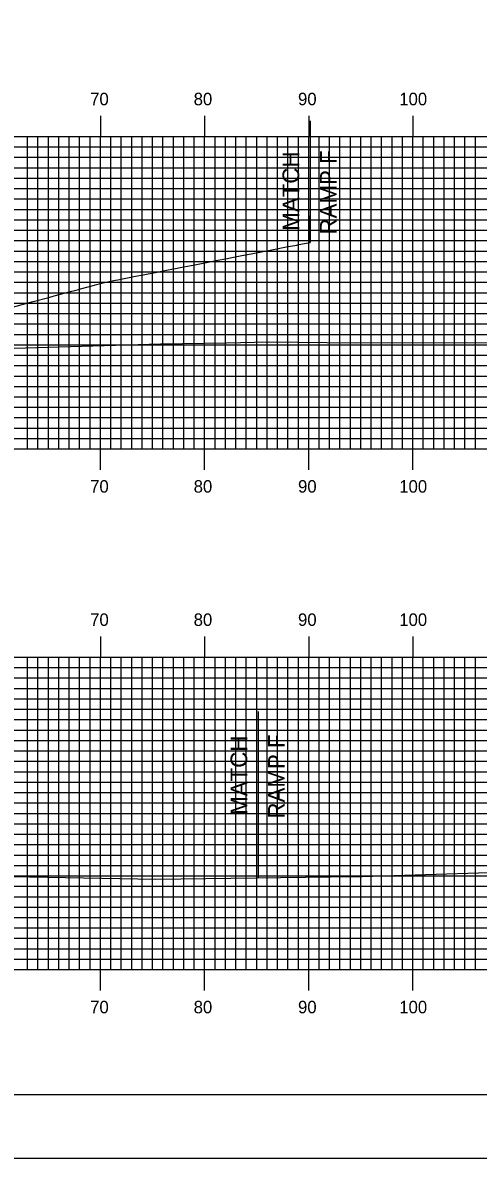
# Model space of a CAD drawing. Extents: x 1757856 to 1758199, y 442591 to 442811.
# Drawn here: x 1758084.2 to 1758127.9, y 442590.5 to 442699.6 of the extents above; entities that cross this region are included whole.
import ezdxf

# ---------------------------------------------------------------- set-up
doc = ezdxf.new("R2010")
doc.units = 0
for name, color, linetype in [('ANNOTATION', 7, 'Continuous'), ('BORDER', 7, 'Continuous'), ('D_Roadway_Centerline', 7, 'Continuous'), ('D_Roadway_FinishedGrade', 7, 'Continuous'), ('D_Roadway_SubGrade', 7, 'Continuous'), ('H_V ANNOTATION', 7, 'Continuous'), ('MAJOR', 7, 'Continuous'), ('MINOR', 7, 'Continuous'), ('PLOT BOUNDARY', 7, 'Continuous'), ('S_Roadway_Centerline', 7, 'Continuous')]:
    doc.layers.add(name, color=color, linetype=linetype)

msp = doc.modelspace()

# ---------------------------------------------------------------- linework, layer by layer
at = {"layer": 'BORDER'}
msp.add_lwpolyline([(1757872.02, 442596.67), (1758192.02, 442596.67), (1758192.02, 442806.67), (1757872.02, 442806.67)], close=True, dxfattribs=at)
at = {"layer": 'D_Roadway_Centerline'}
msp.add_lwpolyline([(1758083.16, 442672.28), (1758084.46, 442672.63), (1758085.17, 442672.82), (1758086.67, 442673.22), (1758087.17, 442673.36), (1758088.86, 442673.81), (1758089.15, 442673.89), (1758089.64, 442674.02), (1758089.7, 442674.03), (1758091.05, 442674.39), (1758091.12, 442674.41), (1758092.15, 442674.68), (1758093.07, 442674.87), (1758093.3, 442674.91), (1758095, 442675.25), (1758095.71, 442675.38), (1758096.87, 442675.61), (1758096.89, 442675.62), (1758096.91, 442675.62), (1758098.12, 442675.86), (1758098.81, 442675.99), (1758099.26, 442676.08), (1758100.69, 442676.36), (1758101.47, 442676.51), (1758102.56, 442676.72), (1758102.71, 442676.75), (1758103.81, 442676.97), (1758104.25, 442677.05), (1758104.41, 442677.08), (1758105.04, 442677.21), (1758106.25, 442677.44), (1758107.08, 442677.6), (1758108.07, 442677.79), (1758109.47, 442678.06), (1758109.87, 442678.14), (1758110.46, 442678.25), (1758110.55, 442678.27), (1758110.67, 442678.29), (1758111.75, 442678.5)], dxfattribs=at)
at = {"layer": 'D_Roadway_FinishedGrade'}
msp.add_line((1758111.75, 442678.5), (1758111.75, 442681.05), dxfattribs=at)
at = {"layer": 'D_Roadway_SubGrade'}
for p, q in [((1758111.75, 442690.19), (1758111.75, 442678.5)), ((1758106.76, 442633.44), (1758106.76, 442617.49))]:
    msp.add_line(p, q, dxfattribs=at)
at = {"layer": 'MAJOR'}
for p, q in [((1758091.62, 442690.67), (1758091.62, 442688.67)), ((1758101.62, 442690.67), (1758101.62, 442688.67)), ((1758111.62, 442690.67), (1758111.62, 442688.67)), ((1758121.62, 442690.67), (1758121.62, 442688.67)), ((1757881.62, 442688.67), (1758161.62, 442688.67)), ((1757881.62, 442688.67), (1758161.62, 442688.67)), ((1758091.62, 442658.67), (1758091.62, 442688.67)), ((1758101.62, 442658.67), (1758101.62, 442688.67)), ((1758111.62, 442658.67), (1758111.62, 442688.67)), ((1758121.62, 442658.67), (1758121.62, 442688.67)), ((1757881.62, 442683.67), (1758161.62, 442683.67)), ((1757881.62, 442678.67), (1758161.62, 442678.67)), ((1757881.62, 442673.67), (1758161.62, 442673.67)), ((1757881.62, 442668.67), (1758161.62, 442668.67)), ((1757881.62, 442663.67), (1758161.62, 442663.67)), ((1757881.62, 442658.67), (1758161.62, 442658.67)), ((1757881.62, 442658.67), (1758161.62, 442658.67)), ((1758091.62, 442656.66), (1758091.62, 442658.67)), ((1758101.62, 442656.66), (1758101.62, 442658.67)), ((1758111.62, 442656.66), (1758111.62, 442658.67)), ((1758121.62, 442656.66), (1758121.62, 442658.67)), ((1758091.62, 442640.67), (1758091.62, 442638.67)), ((1758101.62, 442640.67), (1758101.62, 442638.67)), ((1758111.62, 442640.67), (1758111.62, 442638.67)), ((1758121.62, 442640.67), (1758121.62, 442638.67)), ((1757881.62, 442638.67), (1758161.62, 442638.67)), ((1757881.62, 442638.67), (1758161.62, 442638.67)), ((1758091.62, 442608.67), (1758091.62, 442638.67)), ((1758101.62, 442608.67), (1758101.62, 442638.67)), ((1758111.62, 442608.67), (1758111.62, 442638.67)), ((1758121.62, 442608.67), (1758121.62, 442638.67)), ((1757881.62, 442633.67), (1758161.62, 442633.67)), ((1757881.62, 442628.67), (1758161.62, 442628.67)), ((1757881.62, 442623.67), (1758161.62, 442623.67)), ((1757881.62, 442618.67), (1758161.62, 442618.67)), ((1757881.62, 442613.67), (1758161.62, 442613.67)), ((1757881.62, 442608.67), (1758161.62, 442608.67)), ((1757881.62, 442608.67), (1758161.62, 442608.67)), ((1758091.62, 442606.66), (1758091.62, 442608.67)), ((1758101.62, 442606.66), (1758101.62, 442608.67)), ((1758111.62, 442606.66), (1758111.62, 442608.67)), ((1758121.62, 442606.66), (1758121.62, 442608.67))]:
    msp.add_line(p, q, dxfattribs=at)
at = {"layer": 'MINOR'}
for p, q in [((1758084.62, 442658.67), (1758084.62, 442688.67)), ((1758085.62, 442658.67), (1758085.62, 442688.67)), ((1758086.62, 442658.67), (1758086.62, 442688.67)), ((1758087.62, 442658.67), (1758087.62, 442688.67)), ((1758088.62, 442658.67), (1758088.62, 442688.67)), ((1758089.62, 442658.67), (1758089.62, 442688.67)), ((1758090.62, 442658.67), (1758090.62, 442688.67)), ((1758092.62, 442658.67), (1758092.62, 442688.67)), ((1758093.62, 442658.67), (1758093.62, 442688.67)), ((1758094.62, 442658.67), (1758094.62, 442688.67)), ((1758095.62, 442658.67), (1758095.62, 442688.67)), ((1758096.62, 442658.67), (1758096.62, 442688.67)), ((1758097.62, 442658.67), (1758097.62, 442688.67)), ((1758098.62, 442658.67), (1758098.62, 442688.67)), ((1758099.62, 442658.67), (1758099.62, 442688.67)), ((1758100.62, 442658.67), (1758100.62, 442688.67)), ((1758102.62, 442658.67), (1758102.62, 442688.67)), ((1758103.62, 442658.67), (1758103.62, 442688.67)), ((1758104.62, 442658.67), (1758104.62, 442688.67)), ((1758105.62, 442658.67), (1758105.62, 442688.67)), ((1758106.62, 442658.67), (1758106.62, 442688.67)), ((1758107.62, 442658.67), (1758107.62, 442688.67)), ((1758108.62, 442658.67), (1758108.62, 442688.67)), ((1758109.62, 442658.67), (1758109.62, 442688.67)), ((1758110.62, 442658.67), (1758110.62, 442688.67)), ((1758112.62, 442658.67), (1758112.62, 442688.67)), ((1758113.62, 442658.67), (1758113.62, 442688.67)), ((1758114.62, 442658.67), (1758114.62, 442688.67)), ((1758115.62, 442658.67), (1758115.62, 442688.67)), ((1758116.62, 442658.67), (1758116.62, 442688.67)), ((1758117.62, 442658.67), (1758117.62, 442688.67)), ((1758118.62, 442658.67), (1758118.62, 442688.67)), ((1758119.62, 442658.67), (1758119.62, 442688.67)), ((1758120.62, 442658.67), (1758120.62, 442688.67)), ((1758122.62, 442658.67), (1758122.62, 442688.67)), ((1758123.62, 442658.67), (1758123.62, 442688.67)), ((1758124.62, 442658.67), (1758124.62, 442688.67)), ((1758125.62, 442658.67), (1758125.62, 442688.67)), ((1758126.62, 442658.67), (1758126.62, 442688.67)), ((1758127.62, 442658.67), (1758127.62, 442688.67)), ((1757881.62, 442687.67), (1758161.62, 442687.67)), ((1757881.62, 442686.67), (1758161.62, 442686.67)), ((1757881.62, 442685.67), (1758161.62, 442685.67)), ((1757881.62, 442684.67), (1758161.62, 442684.67)), ((1757881.62, 442682.67), (1758161.62, 442682.67)), ((1757881.62, 442681.67), (1758161.62, 442681.67)), ((1757881.62, 442680.67), (1758161.62, 442680.67)), ((1757881.62, 442679.67), (1758161.62, 442679.67)), ((1757881.62, 442677.67), (1758161.62, 442677.67)), ((1757881.62, 442676.67), (1758161.62, 442676.67)), ((1757881.62, 442675.67), (1758161.62, 442675.67)), ((1757881.62, 442674.67), (1758161.62, 442674.67)), ((1757881.62, 442672.67), (1758161.62, 442672.67)), ((1757881.62, 442671.67), (1758161.62, 442671.67)), ((1757881.62, 442670.67), (1758161.62, 442670.67)), ((1757881.62, 442669.67), (1758161.62, 442669.67)), ((1757881.62, 442667.67), (1758161.62, 442667.67)), ((1757881.62, 442666.67), (1758161.62, 442666.67)), ((1757881.62, 442665.67), (1758161.62, 442665.67)), ((1757881.62, 442664.67), (1758161.62, 442664.67)), ((1757881.62, 442662.67), (1758161.62, 442662.67)), ((1757881.62, 442661.67), (1758161.62, 442661.67)), ((1757881.62, 442660.67), (1758161.62, 442660.67)), ((1757881.62, 442659.67), (1758161.62, 442659.67)), ((1758084.62, 442608.67), (1758084.62, 442638.67)), ((1758085.62, 442608.67), (1758085.62, 442638.67)), ((1758086.62, 442608.67), (1758086.62, 442638.67)), ((1758087.62, 442608.67), (1758087.62, 442638.67)), ((1758088.62, 442608.67), (1758088.62, 442638.67)), ((1758089.62, 442608.67), (1758089.62, 442638.67)), ((1758090.62, 442608.67), (1758090.62, 442638.67)), ((1758092.62, 442608.67), (1758092.62, 442638.67)), ((1758093.62, 442608.67), (1758093.62, 442638.67)), ((1758094.62, 442608.67), (1758094.62, 442638.67)), ((1758095.62, 442608.67), (1758095.62, 442638.67)), ((1758096.62, 442608.67), (1758096.62, 442638.67)), ((1758097.62, 442608.67), (1758097.62, 442638.67)), ((1758098.62, 442608.67), (1758098.62, 442638.67)), ((1758099.62, 442608.67), (1758099.62, 442638.67)), ((1758100.62, 442608.67), (1758100.62, 442638.67)), ((1758102.62, 442608.67), (1758102.62, 442638.67)), ((1758103.62, 442608.67), (1758103.62, 442638.67)), ((1758104.62, 442608.67), (1758104.62, 442638.67)), ((1758105.62, 442608.67), (1758105.62, 442638.67)), ((1758106.62, 442608.67), (1758106.62, 442638.67)), ((1758107.62, 442608.67), (1758107.62, 442638.67)), ((1758108.62, 442608.67), (1758108.62, 442638.67)), ((1758109.62, 442608.67), (1758109.62, 442638.67)), ((1758110.62, 442608.67), (1758110.62, 442638.67)), ((1758112.62, 442608.67), (1758112.62, 442638.67)), ((1758113.62, 442608.67), (1758113.62, 442638.67)), ((1758114.62, 442608.67), (1758114.62, 442638.67)), ((1758115.62, 442608.67), (1758115.62, 442638.67)), ((1758116.62, 442608.67), (1758116.62, 442638.67)), ((1758117.62, 442608.67), (1758117.62, 442638.67)), ((1758118.62, 442608.67), (1758118.62, 442638.67)), ((1758119.62, 442608.67), (1758119.62, 442638.67)), ((1758120.62, 442608.67), (1758120.62, 442638.67)), ((1758122.62, 442608.67), (1758122.62, 442638.67)), ((1758123.62, 442608.67), (1758123.62, 442638.67)), ((1758124.62, 442608.67), (1758124.62, 442638.67)), ((1758125.62, 442608.67), (1758125.62, 442638.67)), ((1758126.62, 442608.67), (1758126.62, 442638.67)), ((1758127.62, 442608.67), (1758127.62, 442638.67)), ((1757881.62, 442637.67), (1758161.62, 442637.67)), ((1757881.62, 442636.67), (1758161.62, 442636.67)), ((1757881.62, 442635.67), (1758161.62, 442635.67)), ((1757881.62, 442634.67), (1758161.62, 442634.67)), ((1757881.62, 442632.67), (1758161.62, 442632.67)), ((1757881.62, 442631.67), (1758161.62, 442631.67)), ((1757881.62, 442630.67), (1758161.62, 442630.67)), ((1757881.62, 442629.67), (1758161.62, 442629.67)), ((1757881.62, 442627.67), (1758161.62, 442627.67)), ((1757881.62, 442626.67), (1758161.62, 442626.67)), ((1757881.62, 442625.67), (1758161.62, 442625.67)), ((1757881.62, 442624.67), (1758161.62, 442624.67)), ((1757881.62, 442622.67), (1758161.62, 442622.67)), ((1757881.62, 442621.67), (1758161.62, 442621.67)), ((1757881.62, 442620.67), (1758161.62, 442620.67)), ((1757881.62, 442619.67), (1758161.62, 442619.67)), ((1757881.62, 442617.67), (1758161.62, 442617.67)), ((1757881.62, 442616.67), (1758161.62, 442616.67)), ((1757881.62, 442615.67), (1758161.62, 442615.67)), ((1757881.62, 442614.67), (1758161.62, 442614.67)), ((1757881.62, 442612.67), (1758161.62, 442612.67)), ((1757881.62, 442611.67), (1758161.62, 442611.67)), ((1757881.62, 442610.67), (1758161.62, 442610.67)), ((1757881.62, 442609.67), (1758161.62, 442609.67))]:
    msp.add_line(p, q, dxfattribs=at)
at = {"layer": 'PLOT BOUNDARY'}
msp.add_lwpolyline([(1757855.84, 442590.55), (1758195.84, 442590.55), (1758195.84, 442810.55), (1757855.84, 442810.55)], close=True, dxfattribs=at)
at = {"layer": 'S_Roadway_Centerline'}
for points in [[(1758080.06, 442668.24), (1758097.4, 442668.75), (1758103.71, 442668.85), (1758107.75, 442668.96), (1758116.17, 442668.84), (1758126.78, 442668.88), (1758129.7, 442668.86), (1758139.58, 442668.71), (1758145.82, 442668.77), (1758159.27, 442668.79), (1758161.62, 442668.79)], [(1758077.01, 442617.74), (1758084.81, 442617.57), (1758096.94, 442617.36), (1758116.11, 442617.6), (1758116.52, 442617.61), (1758116.62, 442617.61), (1758116.75, 442617.61), (1758135.04, 442618.18), (1758146.69, 442618.22), (1758150.89, 442618.14), (1758161.62, 442618.43)]]:
    msp.add_lwpolyline(points, dxfattribs=at)

# ---------------------------------------------------------------- texts
at = {"layer": 'ANNOTATION'}
for s, p in [('MATCH', (1758110.7, 442679.62)), ('RAMP F', (1758114.3, 442679.26)), ('MATCH', (1758105.71, 442623.53)), ('RAMP F', (1758109.31, 442623.17))]:
    msp.add_text(s, height=1.6, rotation=90, dxfattribs=at).set_placement(p)
at = {"layer": 'H_V ANNOTATION'}
for s, p in [('70', (1758090.63, 442691.67)), ('80', (1758100.57, 442691.67)), ('90', (1758110.59, 442691.67)), ('100', (1758120.31, 442691.67)), ('70', (1758090.63, 442654.47)), ('80', (1758100.57, 442654.47)), ('90', (1758110.59, 442654.47)), ('100', (1758120.31, 442654.47)), ('70', (1758090.63, 442641.67)), ('80', (1758100.57, 442641.67)), ('90', (1758110.59, 442641.67)), ('100', (1758120.31, 442641.67)), ('70', (1758090.63, 442604.47)), ('80', (1758100.57, 442604.47)), ('90', (1758110.59, 442604.47)), ('100', (1758120.31, 442604.47))]:
    msp.add_text(s, height=1.2, dxfattribs=at).set_placement(p)

doc.saveas('drawing.dxf')
